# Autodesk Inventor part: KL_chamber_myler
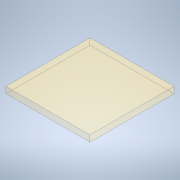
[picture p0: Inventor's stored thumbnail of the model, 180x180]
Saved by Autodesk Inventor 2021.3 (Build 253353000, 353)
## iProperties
Created: 2021-12
Part Number: KL_chamber_myler
Material: ポリカーボネート、クリア
Document SubType Name: Modeling
Designer: kengo
Density: 1.2 g/cm^3
Appearance: ポリカーボネート - クリア
Author: kengo
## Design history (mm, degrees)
sketch "スケッチ1"
  geometry: L1 (-368.479, 83.476)-(817.021, 83.476); L2 (817.021, 83.476)-(817.021, -6.524); L3 (817.021, -6.524)-(-368.479, -6.524); L4 (-368.479, -6.524)-(-368.479, 83.476); 1 further point
  constraints: 8 end point, 2 parallel, 1 horizontal, 1 perpendicular
  dimensions: "d0" = 1185.5 distance of L1.start L1.end; "d1" = 90 distance of L3.end L1.start
extrude "押し出し1" new body sketch "スケッチ1" distance "d2" = 1185.5; taper "d3" = 0 deg
node "ソリッド1"
